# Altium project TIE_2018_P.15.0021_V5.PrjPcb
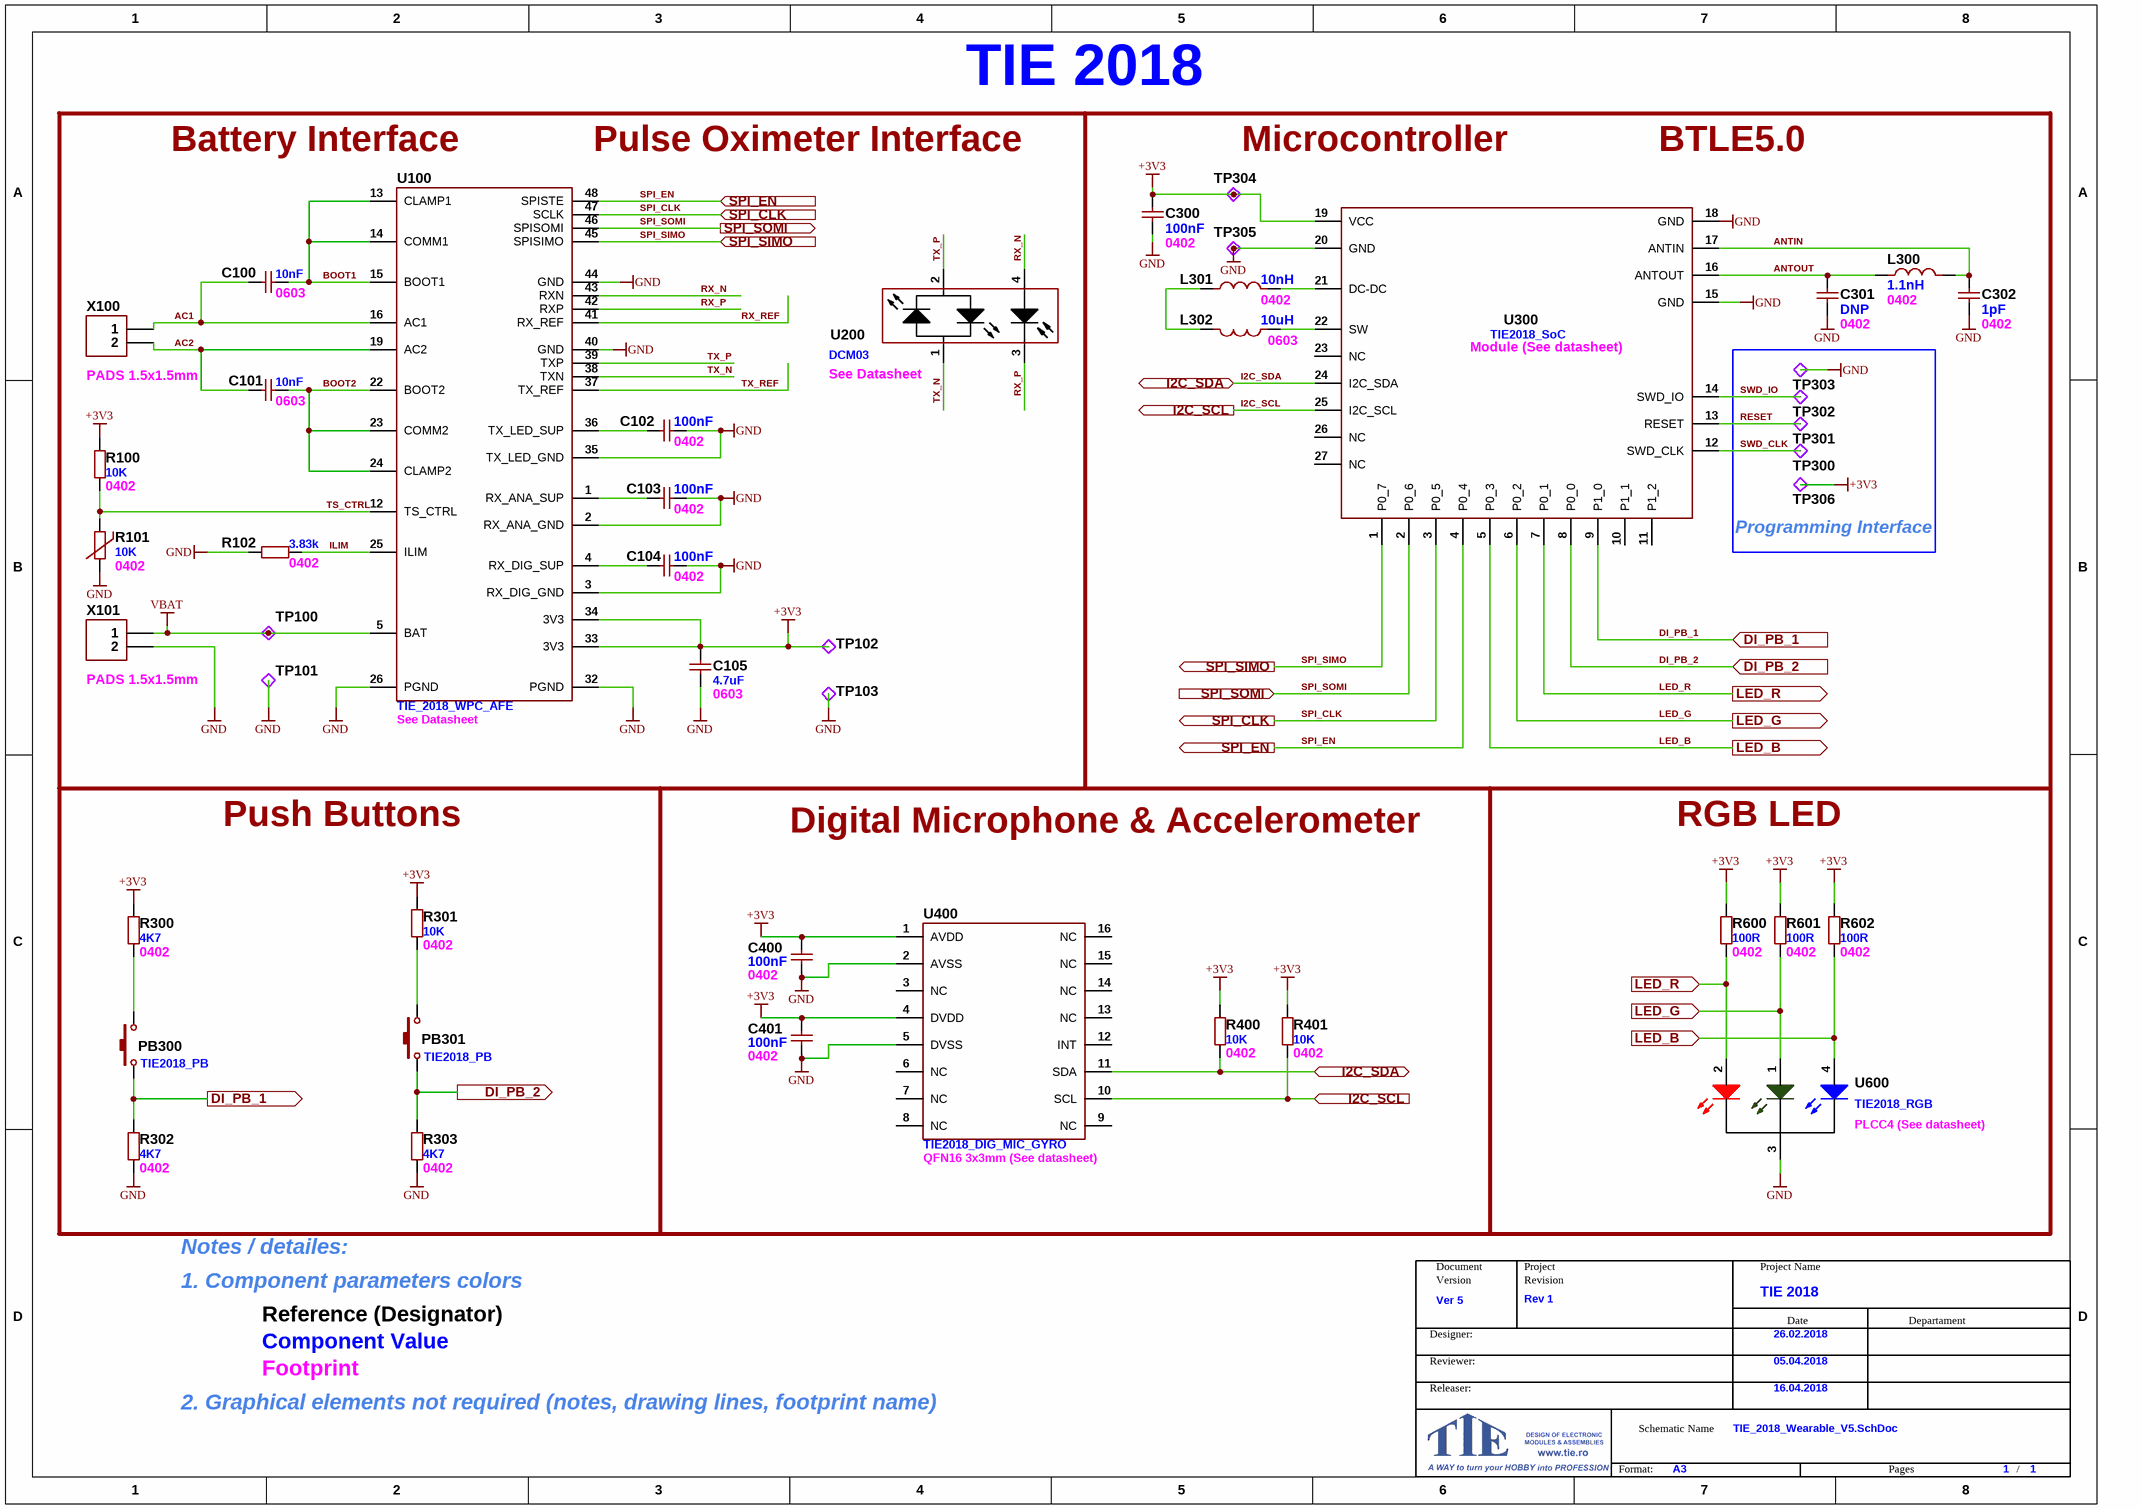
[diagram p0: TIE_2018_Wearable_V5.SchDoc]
1.ProjectName: TIE 2018; 1.ProjectStatus: Reviewd; 2.GlobalProjectTeam: TEAM; 6.ECN: N/A; 7.ProjectRevision: Rev 1; 8.Version: Ver 5; 9.Prew_Version: Ver 4; 010.SCH: TIE_2018_Wearable; 011.BOM: TIE_2018_Wearable; 012.ASSY: TIE_2018_Wearable; 013.PCB: TIE_2018_Wearable; 014.PNL: TIE_2018_Wearable; 015.TDS: ANEX_2; 016.DRW_PCB: TIE_2018_Wearable; 017.DRW_PNL: TIE_2018_Wearable; 018.Design Date: 26.02.2018; 019.Review Date: 05.04.2018; 020.Approuve Date: 16.04.2018; 024.SheetTotal: 1; 025.Format: A3; ASY_Variant_1: ASSY_V_01_15.0021; ASY_Variant_2: ASSY_V_02_15.0021; ASY_Variant_3: ASSY_V_03_15.000x; ASY_Variant_4: ASSY_V_04_15.0021; ASY_Variant_5: ASSY_V_05_15.0021; BOM_V1: BOM_V1_15.0021; BOM_V2: BOM_V2_15.0021; BOM_V3: BOM_V3_15.0021; BOM_V4: BOM_V2_15.0021; BOM_V5: BOM_V5_15.0021; Scale: 1:1; Variant_1: SCH_V_01_15.0021; Variant_2: SCH_V_02_15.0021; Variant_3: SCH_V_03_15.0021; Variant_4: SCH_V_04_15.0021; Variant_5: SCH_V_05_15.0021; Variant_Max: V_All
1 sheet, 47 parts. Net scope: flat (ports and power ports of the same name join across sheets).
Board file: TIE_2018_V5.PcbDoc

## Sheet TIE_2018_Wearable_V5.SchDoc
size A3; DocumentNumber: 1; SheetNumber: 1; SheetTotal: 8

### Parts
C100  10nF  Footprint Name: 0603  [CAPC1608_0603H080]
C101  10nF  Footprint Name: 0603  [CAPC1608_0603H080]
C102  100nF  Footprint Name: 0402  [CAPC1005_0402H050]
C103  100nF  Footprint Name: 0402  [CAPC1005_0402H050]
C104  100nF  Footprint Name: 0402  [CAPC1005_0402H050]
C105  4.7uF  Footprint Name: 0603  [CAPC1608_0603H080]
C300  100nF  Footprint Name: 0402  [CAPC1005_0402H050]
C301  DNP  Footprint Name: 0402  [CAPC1005_0402H050]
C302  1pF  Footprint Name: 0402  [CAPC1005_0402H050]
C400  100nF  Footprint Name: 0402  [CAPC1005_0402H050]
C401  100nF  Footprint Name: 0402  [CAPC1005_0402H050]
FRAME?  (no value)  (graphical)
L300  1.1nH  Footprint Name: 0402  [INDC1005_0402H050]
L301  10nH  Footprint Name: 0402  [INDC1005_0402H050]
L302  10uH  Footprint Name: 0603  [INDC1608_0603H102]
PB300  TIE2018_PB  [TIE_2018_PUSH_2.5x2.5]
PB301  TIE2018_PB  [TIE_2018_PUSH_2.5x2.5]
R100  10K  Footprint Name: 0402  [RESC1005_0402H035]
R101  10K  Footprint Name: 0402  [RESC1005_0402H035]
R102  3.83k  Footprint Name: 0402  [RESC1005_0402H035]
R300  4K7  Footprint Name: 0402  [RESC1005_0402H035]
R301  10K  Footprint Name: 0402  [RESC1005_0402H035]
R302  4K7  Footprint Name: 0402  [RESC1005_0402H035]
R303  4K7  Footprint Name: 0402  [RESC1005_0402H035]
R400  10K  Footprint Name: 0402  [RESC1005_0402H035]
R401  10K  Footprint Name: 0402  [RESC1005_0402H035]
R600  100R  Footprint Name: 0402  [RESC1005_0402H035]
R601  100R  Footprint Name: 0402  [RESC1005_0402H035]
R602  100R  Footprint Name: 0402  [RESC1005_0402H035]
TP100  0.5mm  [TESTPOINT_500]  (value not drawn)
TP101  0.5mm  [TESTPOINT_500]  (value not drawn)
TP102  0.5mm  [TESTPOINT_500]  (value not drawn)
TP103  0.5mm  [TESTPOINT_500]  (value not drawn)
TP300  0.5mm  [TESTPOINT_500]  (value not drawn)
TP301  0.5mm  [TESTPOINT_500]  (value not drawn)
TP302  0.5mm  [TESTPOINT_500]  (value not drawn)
TP303  0.5mm  [TESTPOINT_500]  (value not drawn)
TP304  0.5mm  [TESTPOINT_500]  (value not drawn)
TP305  0.5mm  [TESTPOINT_500]  (value not drawn)
TP306  0.5mm  [TESTPOINT_500]  (value not drawn)
U100  TIE_2018_WPC_AFE  Footprint Name: See Datasheet  [TIE2018_WPC-AFE]
U200  DCM03  Footprint Name: See Datasheet  [DCM03]
U300  TIE2018_SoC  Footprint Name: Module (See datasheet)  [TIE2018-SoC]
U400  TIE2018_DIG_MIC_GYRO  Footprint Name: QFN16 3x3mm (See datasheet)  [QFN16_P500_3000x3000x750_L]
U600  TIE2018_RGB  Footprint Name: PLCC4 (See datasheet)  [PLCC4_LED]
X100  PADS 1.5x1.5mm  [Contact Pads]
X101  Footprint Name: PADS 1.5x1.5mm  [Contact Pads]  (hidden comment: Header 2)

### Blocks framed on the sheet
Programming Interface: TP300-TP303 TP306

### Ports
DI_PB_1 (in), DI_PB_1 (out), DI_PB_2 (in), DI_PB_2 (out), I2C_SCL (in), I2C_SCL (out), I2C_SDA (bidir), LED_B (in), LED_B (out), LED_G (in), LED_G (out), LED_R (in), LED_R (out), SPI_CLK (in), SPI_CLK (out), SPI_EN (in), SPI_EN (out), SPI_SIMO (in), SPI_SIMO (out), SPI_SOMI (in), SPI_SOMI (out)

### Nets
+3V3: C105.2 C300.1 C400.1 C401.1 R100.2 R300.1 R301.1 R400.1 R401.1 R600.1 R601.1 R602.1 TP102.1 TP304.1 TP306.1 U100.33(3V3) U100.34(3V3) U300.19(VCC) U400.1(AVDD) U400.4(DVDD)
GND: C102.1 C103.1 C104.1 C105.1 C300.2 C301.1 C302.1 C400.2 C401.2 R101.2 R102.1 R302.2 R303.2 TP101.1 TP103.1 TP303.1 TP305.1 U100.2(RX_ANA_GND) U100.3(RX_DIG_GND) U100.26(PGND) U100.32(PGND) U100.35(TX_LED_GND) U100.40(GND) U100.44(GND) U300.15(GND) U300.18(GND) U300.20(GND) U400.2(AVSS) U400.5(DVSS) U600.3(CK) X101.2
VBAT: TP100.1 U100.5(BAT) X101.1
AC1: C100.1 U100.16(AC1) X100.1
AC2: C101.1 U100.19(AC2) X100.2
ANTIN: C302.2 L300.2 U300.17(ANTIN)
ANTOUT: C301.2 L300.1 U300.16(ANTOUT)
BOOT1: C100.2 U100.13(CLAMP1) U100.14(COMM1) U100.15(BOOT1)
BOOT2: C101.2 U100.22(BOOT2) U100.23(COMM2) U100.24(CLAMP2)
DI_PB_1: PB300.2 R302.1 U300.9(P1_0) ; port DI_PB_1
DI_PB_2: PB301.2 R303.1 U300.8(P0_0) ; port DI_PB_2
I2C_SCL: R401.2 U300.25(I2C_SCL) U400.10(SCL) ; port I2C_SCL
I2C_SDA: R400.2 U300.24(I2C_SDA) U400.11(SDA) ; port I2C_SDA
ILIM: R102.2 U100.25(ILIM)
LED_B: R602.2 U300.5(P0_3) U600.4(B) ; port LED_B
LED_G: R601.2 U300.6(P0_2) U600.1(G) ; port LED_G
LED_R: R600.2 U300.7(P0_1) U600.2(R) ; port LED_R
RESET: TP301.1 U300.13(RESET)
RX_N: U100.43(RXN) U200.4
RX_P: U100.42(RXP) U200.3
RX_REF: U100.41(RX_REF)
SPI_CLK: U100.47(SCLK) U300.3(P0_5) ; port SPI_CLK
SPI_EN: U100.48(SPISTE) U300.4(P0_4) ; port SPI_EN
SPI_SIMO: U100.45(SPISIMO) U300.1(P0_7) ; port SPI_SIMO
SPI_SOMI: U100.46(SPISOMI) U300.2(P0_6) ; port SPI_SOMI
SWD_CLK: TP300.1 U300.12(SWD_CLK)
SWD_IO: TP302.1 U300.14(SWD_IO)
TS_CTRL: R100.1 R101.1 U100.12(TS_CTRL)
TX_N: U100.38(TXN) U200.1
TX_P: U100.39(TXP) U200.2
TX_REF: U100.37(TX_REF)
NetC102_2: C102.2 U100.36(TX_LED_SUP)
NetC103_2: C103.2 U100.1(RX_ANA_SUP)
NetC104_2: C104.2 U100.4(RX_DIG_SUP)
NetL301_1: L301.1 L302.2
NetL301_2: L301.2 U300.21(DC-DC)
NetL302_1: L302.1 U300.22(SW)
NetPB300_1: PB300.1 R300.2
NetPB301_1: PB301.1 R301.2

Not connected (* = marked no-connect by the designer): U300 10(P1_1) 11(P1_2) 23(NC) 26(NC) 27(NC); U400 3(NC) 6(NC) 7(NC) 8(NC) 9(NC) 12(INT) 13(NC) 14(NC) 15(NC) 16(NC)

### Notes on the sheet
- (near U100) Battery Interface
- (near U100) Pulse Oximeter Interface
- (near TP304) Microcontroller
- BTLE5.0
- Push Buttons
- Digital Microphone & Accelerometer
- RGB LED
- Notes / detailes:
- 1. Component parameters colors
- Reference (Designator)
- Footprint
- Component Value
- 2. Graphical elements not required (notes, drawing lines, footprint name)

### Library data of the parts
C100-C105 C300-C302 C400 C401 = Cap
FRAME? = FRAME_TIE: Frame Schematic
L300-L302 = Inductor
PB300 PB301 = PushButton
R100 R102 R300-R303 R400 R401 R600-R602 = Res
R101 = Res_Thermistor
TP100-TP103 TP300-TP306 = TestPoint_0500
U100 = TIE2018_WPC_AFE
U200 = TIE2018_PULSE
X100 = Header 2

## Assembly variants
V_01: all parts fitted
